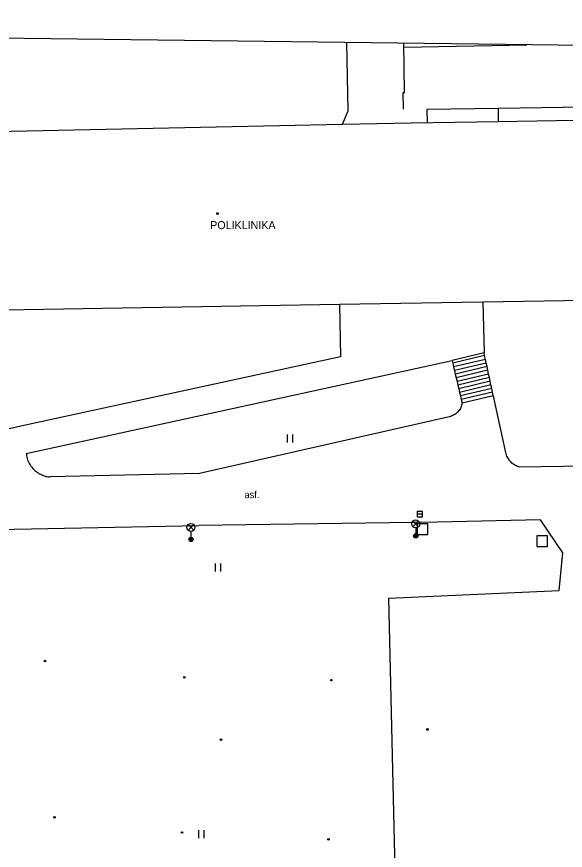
# Model space of a CAD drawing. Extents: x -641829 to -641525, y -1114855 to -1114359.
# Drawn here: x -641663.2 to -641611.8, y -1114437 to -1114358.9 of the extents above; entities that cross this region are included whole.
import ezdxf

# ---------------------------------------------------------------- set-up
doc = ezdxf.new("R2010")
doc.units = 0
for name, color, linetype in [('Vrstva 1', 7, 'Continuous'), ('Vrstva 10', 7, 'Continuous'), ('Vrstva 11', 7, 'Continuous'), ('Vrstva 20', 7, 'Continuous'), ('Vrstva 26', 7, 'Continuous'), ('Vrstva 27', 7, 'Continuous'), ('Vrstva 33', 7, 'Continuous'), ('Vrstva 36', 7, 'Continuous'), ('Vrstva 39', 7, 'Continuous'), ('Vrstva 40', 7, 'Continuous'), ('Vrstva 41', 7, 'Continuous'), ('Vrstva 5', 7, 'Continuous')]:
    doc.layers.add(name, color=color, linetype=linetype)

msp = doc.modelspace()

# ---------------------------------------------------------------- linework, layer by layer
at = {"layer": 'Vrstva 1'}
msp.add_line((-641525.3, -1114362.64), (-641828.67, -1114358.89), dxfattribs=at)
at = {"layer": 'Vrstva 10'}
for p, q in [((-641626.96, -1114361.75), (-641615.43, -1114361.526)), ((-641593.11, -1114367.12), (-641618.09, -1114367.49))]:
    msp.add_line(p, q, dxfattribs=at)
at = {"layer": 'Vrstva 11'}
for p, q in [((-641618.09, -1114367.49), (-641624.79, -1114367.6)), ((-641624.79, -1114367.6), (-641624.77, -1114368.82)), ((-641618.07, -1114368.71), (-641618.09, -1114367.49)), ((-641633, -1114385.83), (-641632.89, -1114390.76)), ((-641619.55, -1114385.61), (-641619.44, -1114390.4)), ((-641632.89, -1114390.76), (-641662.86, -1114397.27)), ((-641619.44, -1114390.4), (-641622.44, -1114391.11)), ((-641619.39, -1114390.66), (-641622.38, -1114391.37)), ((-641619.39, -1114390.66), (-641619.44, -1114390.4)), ((-641619.31, -1114391.01), (-641619.39, -1114390.66)), ((-641662.35, -1114399.84), (-641622.44, -1114391.11)), ((-641622.44, -1114391.11), (-641622.38, -1114391.37)), ((-641622.38, -1114391.37), (-641622.3, -1114391.71)), ((-641619.31, -1114391.01), (-641622.3, -1114391.71)), ((-641619.24, -1114391.35), (-641622.22, -1114392.05)), ((-641619.24, -1114391.35), (-641619.31, -1114391.01)), ((-641619.16, -1114391.69), (-641619.24, -1114391.35)), ((-641622.3, -1114391.71), (-641622.22, -1114392.05)), ((-641622.22, -1114392.05), (-641622.14, -1114392.4)), ((-641619.16, -1114391.69), (-641622.14, -1114392.4)), ((-641622.14, -1114392.4), (-641622.05, -1114392.74)), ((-641619.09, -1114392.03), (-641622.05, -1114392.74)), ((-641619.02, -1114392.38), (-641621.97, -1114393.08)), ((-641619.09, -1114392.03), (-641619.16, -1114391.69)), ((-641619.02, -1114392.38), (-641619.09, -1114392.03)), ((-641618.94, -1114392.72), (-641619.02, -1114392.38)), ((-641622.05, -1114392.74), (-641621.97, -1114393.08)), ((-641621.97, -1114393.08), (-641621.89, -1114393.42)), ((-641618.94, -1114392.72), (-641621.89, -1114393.42)), ((-641618.87, -1114393.06), (-641621.81, -1114393.76)), ((-641618.87, -1114393.06), (-641618.94, -1114392.72)), ((-641618.79, -1114393.4), (-641618.87, -1114393.06)), ((-641621.89, -1114393.42), (-641621.81, -1114393.76)), ((-641621.81, -1114393.76), (-641621.73, -1114394.1)), ((-641618.79, -1114393.4), (-641621.73, -1114394.1)), ((-641618.72, -1114393.74), (-641621.65, -1114394.44)), ((-641618.72, -1114393.74), (-641618.79, -1114393.4)), ((-641618.64, -1114394.09), (-641618.72, -1114393.74)), ((-641621.73, -1114394.1), (-641621.65, -1114394.44)), ((-641621.65, -1114394.44), (-641621.57, -1114394.78)), ((-641618.64, -1114394.09), (-641621.57, -1114394.78)), ((-641618.57, -1114394.43), (-641621.49, -1114395.12)), ((-641618.57, -1114394.43), (-641618.64, -1114394.09)), ((-641618.56, -1114394.47), (-641618.57, -1114394.43)), ((-641617.41, -1114399.74), (-641618.56, -1114394.47)), ((-641621.62, -1114395.51), (-641621.66, -1114395.61)), ((-641621.57, -1114395.41), (-641621.62, -1114395.51)), ((-641621.57, -1114394.78), (-641621.49, -1114395.12)), ((-641621.54, -1114395.31), (-641621.57, -1114395.41)), ((-641621.51, -1114395.21), (-641621.54, -1114395.31)), ((-641621.49, -1114395.12), (-641621.51, -1114395.21)), ((-641622.45, -1114396.31), (-641622.55, -1114396.35)), ((-641622.35, -1114396.27), (-641622.45, -1114396.31)), ((-641622.26, -1114396.22), (-641622.35, -1114396.27)), ((-641622.17, -1114396.16), (-641622.26, -1114396.22)), ((-641622.08, -1114396.1), (-641622.17, -1114396.16)), ((-641622, -1114396.03), (-641622.08, -1114396.1)), ((-641621.92, -1114395.95), (-641622, -1114396.03)), ((-641621.85, -1114395.87), (-641621.92, -1114395.95)), ((-641621.78, -1114395.79), (-641621.85, -1114395.87)), ((-641621.72, -1114395.7), (-641621.78, -1114395.79)), ((-641621.66, -1114395.61), (-641621.72, -1114395.7)), ((-641622.55, -1114396.35), (-641646.1, -1114401.7)), ((-641662.86, -1114397.27), (-641685.59, -1114402.49)), ((-641662.35, -1114399.84), (-641662.34, -1114399.91)), ((-641662.34, -1114399.91), (-641662.32, -1114400.04)), ((-641662.32, -1114400.04), (-641662.29, -1114400.17)), ((-641662.29, -1114400.17), (-641662.26, -1114400.3)), ((-641617.38, -1114399.85), (-641617.41, -1114399.74)), ((-641617.34, -1114399.96), (-641617.38, -1114399.85)), ((-641617.3, -1114400.07), (-641617.34, -1114399.96)), ((-641617.25, -1114400.18), (-641617.3, -1114400.07)), ((-641617.19, -1114400.28), (-641617.25, -1114400.18)), ((-641662.26, -1114400.3), (-641662.22, -1114400.43)), ((-641662.22, -1114400.43), (-641662.17, -1114400.55)), ((-641662.17, -1114400.55), (-641662.11, -1114400.67)), ((-641662.11, -1114400.67), (-641662.05, -1114400.79)), ((-641662.05, -1114400.79), (-641661.98, -1114400.9)), ((-641661.98, -1114400.9), (-641661.91, -1114401.01)), ((-641617.13, -1114400.38), (-641617.19, -1114400.28)), ((-641617.06, -1114400.47), (-641617.13, -1114400.38)), ((-641616.99, -1114400.56), (-641617.06, -1114400.47)), ((-641616.91, -1114400.64), (-641616.99, -1114400.56)), ((-641616.82, -1114400.72), (-641616.91, -1114400.64)), ((-641616.73, -1114400.8), (-641616.82, -1114400.72)), ((-641616.64, -1114400.87), (-641616.73, -1114400.8)), ((-641616.54, -1114400.93), (-641616.64, -1114400.87)), ((-641616.44, -1114400.98), (-641616.54, -1114400.93)), ((-641616.34, -1114401.03), (-641616.44, -1114400.98)), ((-641596.55, -1114400.81), (-641616.13, -1114401.11)), ((-641661.91, -1114401.01), (-641661.83, -1114401.12)), ((-641661.83, -1114401.12), (-641661.74, -1114401.22)), ((-641661.74, -1114401.22), (-641661.65, -1114401.32)), ((-641661.65, -1114401.32), (-641661.56, -1114401.41)), ((-641661.56, -1114401.41), (-641661.45, -1114401.49)), ((-641661.45, -1114401.49), (-641661.35, -1114401.57)), ((-641661.35, -1114401.57), (-641661.24, -1114401.65)), ((-641661.24, -1114401.65), (-641661.13, -1114401.72)), ((-641661.13, -1114401.72), (-641661.01, -1114401.78)), ((-641661.01, -1114401.78), (-641660.89, -1114401.84)), ((-641646.1, -1114401.7), (-641660.12, -1114402.03)), ((-641616.23, -1114401.08), (-641616.34, -1114401.03)), ((-641616.13, -1114401.11), (-641616.23, -1114401.08)), ((-641660.89, -1114401.84), (-641660.77, -1114401.89)), ((-641660.77, -1114401.89), (-641660.64, -1114401.93)), ((-641660.64, -1114401.93), (-641660.51, -1114401.97)), ((-641660.51, -1114401.97), (-641660.38, -1114401.99)), ((-641660.38, -1114401.99), (-641660.25, -1114402.01)), ((-641660.25, -1114402.01), (-641660.12, -1114402.03)), ((-641623.83, -1114406.25), (-641646.17, -1114406.59)), ((-641614.14, -1114406.06), (-641623.83, -1114406.25)), ((-641612.06, -1114409.14), (-641614.14, -1114406.06)), ((-641665.75, -1114406.97), (-641646.17, -1114406.59)), ((-641612.41, -1114412.68), (-641612.06, -1114409.14)), ((-641628.37, -1114413.4), (-641612.41, -1114412.68)), ((-641627.59, -1114445.77), (-641628.37, -1114413.4))]:
    msp.add_line(p, q, dxfattribs=at)
at = {"layer": 'Vrstva 20'}
for centre, radius in [((-641660.6, -1114419.28), 0.075), ((-641660.6, -1114419.28), 0.0204), ((-641647.54, -1114420.8), 0.075), ((-641647.54, -1114420.8), 0.0204), ((-641633.76, -1114421.07), 0.075), ((-641633.76, -1114421.07), 0.0204), ((-641624.74, -1114425.69), 0.075), ((-641624.74, -1114425.69), 0.0204), ((-641644.09, -1114426.66), 0.075), ((-641644.09, -1114426.66), 0.0204), ((-641659.7, -1114433.93), 0.075), ((-641659.7, -1114433.93), 0.0204), ((-641647.75, -1114435.35), 0.075), ((-641647.75, -1114435.35), 0.0204), ((-641634.02, -1114435.99), 0.075), ((-641634.02, -1114435.99), 0.0204)]:
    msp.add_circle(centre, radius, dxfattribs=at)
at = {"layer": 'Vrstva 26'}
for points in [[(-641624.72, -1114406.43), (-641625.72, -1114406.43), (-641625.72, -1114407.43), (-641624.72, -1114407.43)], [(-641613.49, -1114407.56), (-641614.49, -1114407.56), (-641614.49, -1114408.56), (-641613.49, -1114408.56)]]:
    msp.add_lwpolyline(points, close=True, dxfattribs=at)
at = {"layer": 'Vrstva 27'}
msp.add_line((-641625.2, -1114405.53), (-641625.7, -1114405.53), dxfattribs=at)
msp.add_lwpolyline([(-641625.2, -1114405.28), (-641625.7, -1114405.28), (-641625.7, -1114405.78), (-641625.2, -1114405.78)], close=True, dxfattribs=at)
at = {"layer": 'Vrstva 33'}
for p, q in [((-641626.104, -1114406.69), (-641625.576, -1114406.16)), ((-641626.104, -1114406.16), (-641625.576, -1114406.69)), ((-641647.174, -1114407.02), (-641646.646, -1114406.49)), ((-641647.174, -1114406.49), (-641646.646, -1114407.02)), ((-641646.91, -1114407.13), (-641646.91, -1114407.88)), ((-641625.84, -1114406.8), (-641625.84, -1114407.55))]:
    msp.add_line(p, q, dxfattribs=at)
for centre, radius in [((-641646.91, -1114406.755), 0.375), ((-641625.84, -1114406.425), 0.375), ((-641646.91, -1114407.88), 0.2), ((-641646.91, -1114407.88), 0.145), ((-641646.91, -1114407.88), 0.0876), ((-641625.84, -1114407.55), 0.2), ((-641625.84, -1114407.55), 0.145), ((-641625.84, -1114407.55), 0.0876)]:
    msp.add_circle(centre, radius, dxfattribs=at)
at = {"layer": 'Vrstva 36'}
for p, q in [((-641637.864, -1114398.802), (-641637.864, -1114398.054)), ((-641637.364, -1114398.802), (-641637.364, -1114398.054)), ((-641644.624, -1114410.882), (-641644.624, -1114410.134)), ((-641644.124, -1114410.882), (-641644.124, -1114410.134)), ((-641646.164, -1114435.884), (-641646.164, -1114435.132)), ((-641645.664, -1114435.884), (-641645.664, -1114435.132))]:
    msp.add_line(p, q, dxfattribs=at)
at = {"layer": 'Vrstva 39'}
for radius in [0.09, 0.0398]:
    msp.add_circle((-641644.41, -1114377.35), radius, dxfattribs=at)
at = {"layer": 'Vrstva 5'}
for p, q in [((-641632.17, -1114367.73), (-641632.294, -1114361.317)), ((-641626.89, -1114366.01), (-641626.968, -1114361.383)), ((-641627.01, -1114366.01), (-641626.89, -1114366.01)), ((-641626.98, -1114367.56), (-641627.01, -1114366.01)), ((-641632.72, -1114368.96), (-641632.17, -1114367.73)), ((-641632.72, -1114368.96), (-641626.27, -1114368.85)), ((-641619.55, -1114385.61), (-641601.66, -1114385.31))]:
    msp.add_line(p, q, dxfattribs=at)
for points in [[(-641669.77, -1114369.75), (-641666.76, -1114369.69), (-641632.72, -1114368.96)], [(-641626.27, -1114368.85), (-641618.07, -1114368.71), (-641601.92, -1114368.43)], [(-641694, -1114386.85), (-641633, -1114385.83), (-641619.55, -1114385.61)]]:
    msp.add_lwpolyline(points, dxfattribs=at)

# ---------------------------------------------------------------- texts
at = {"layer": 'Vrstva 40'}
msp.add_text('asf.', height=0.65, rotation=0.87194, dxfattribs=at).set_placement((-641641.89, -1114404.02))
at = {"layer": 'Vrstva 41'}
msp.add_text('POLIKLINIKA', height=0.75, dxfattribs=at).set_placement((-641645.11, -1114378.8))

doc.saveas('drawing.dxf')
